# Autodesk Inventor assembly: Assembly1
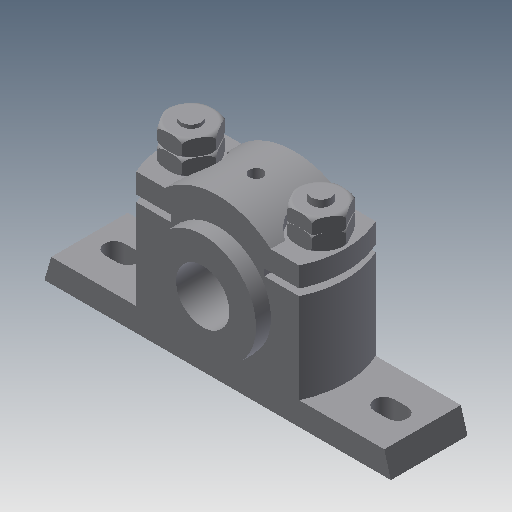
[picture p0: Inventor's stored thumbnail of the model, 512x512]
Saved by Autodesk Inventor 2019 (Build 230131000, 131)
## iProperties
Created: 2015-03
Part Number: Assembly1
Document SubType Name: Assembly
Designer: Sandeep
Author: Sandeep
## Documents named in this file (7)
- E:\_Deepak\Inventor\Projects\Autodesk Inventor_2019_Project\Resources\Inventor_2018_tut\c11_Inv_2019_tut\c11_Inv_tut_2019\c11_tut02_inv\Plummer Block.iam
- E:\_Deepak\Inventor\Projects\Autodesk Inventor_2019_Project\Resources\Inventor_2018_tut\c11_Inv_2019_tut\c11_Inv_tut_2019\c11_tut02_inv\Casting.ipt
- E:\_Deepak\Inventor\Projects\Autodesk Inventor_2019_Project\Resources\Inventor_2018_tut\c11_Inv_2019_tut\c11_Inv_tut_2019\c11_tut02_inv\Brasses.ipt
- E:\_Deepak\Inventor\Projects\Autodesk Inventor_2019_Project\Resources\Inventor_2018_tut\c11_Inv_2019_tut\c11_Inv_tut_2019\c11_tut02_inv\Cap.ipt
- E:\_Deepak\Inventor\Projects\Autodesk Inventor_2019_Project\Resources\Inventor_2018_tut\c11_Inv_2019_tut\c11_Inv_tut_2019\c11_tut02_inv\Bolt.ipt
- E:\_Deepak\Inventor\Projects\Autodesk Inventor_2019_Project\Resources\Inventor_2018_tut\c11_Inv_2019_tut\c11_Inv_tut_2019\c11_tut02_inv\Nut.ipt
- E:\_Deepak\Inventor\Projects\Autodesk Inventor_2019_Project\Resources\Inventor_2018_tut\c11_Inv_2019_tut\c11_Inv_tut_2019\c11_tut02_inv\Lock Nut.ipt
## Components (9 placed, 6 different names)
1. Casting:1 — Mate:1, Mate:2, Insert:1, Insert:2, Angle:1, Angle:2
2. Brasses:1 — Mate:1, Mate:2, Mate:3, Mate:4
3. Cap:1 — Mate:3, Mate:4, Insert:3, Insert:5
4. Bolt:1 — Insert:1, Angle:2
5. Bolt:2 — Insert:2, Angle:1, Mate:5
6. Nut:1 — Insert:5
7. Nut:2 — Insert:3, Insert:4
8. Lock Nut:1 — Insert:4
9. Lock Nut:2 — Mate:5
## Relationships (12: Mate 5, Insert 5, Angle 2)
- Mate:1: Casting:1 ↔ Brasses:1
- Mate:2: Casting:1 ↔ Brasses:1
- Mate:3: Brasses:1 ↔ Cap:1
- Mate:4: Brasses:1 ↔ Cap:1
- Insert:1: Casting:1 ↔ Bolt:1
- Insert:2: Casting:1 ↔ Bolt:2
- Angle:1: Casting:1 ↔ Bolt:2
- Angle:2: Casting:1 ↔ Bolt:1
- Insert:3: Cap:1 ↔ Nut:2
- Insert:4: Nut:2 ↔ Lock Nut:1
- Insert:5: Cap:1 ↔ Nut:1
- Mate:5: Bolt:2 ↔ Lock Nut:2
